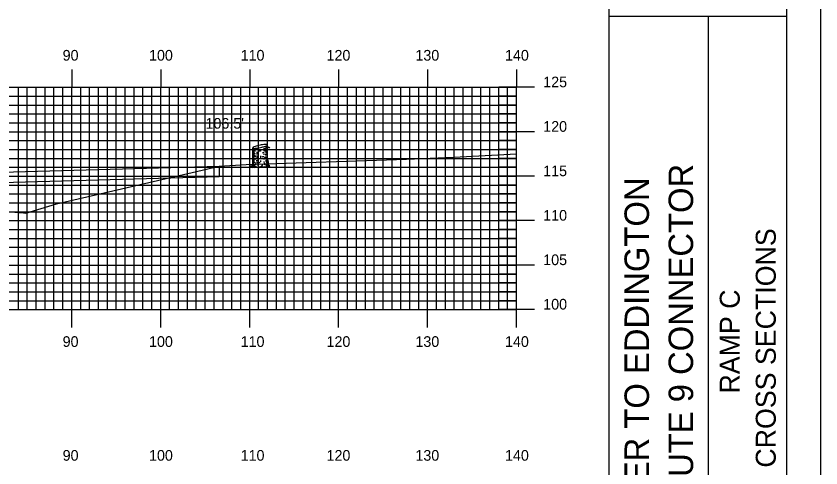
# Model space of a CAD drawing. Extents: x 1685586 to 1685929, y 461260 to 461480.
# Drawn here: x 1685835.5 to 1685926, y 461305.3 to 461356.1 of the extents above; entities that cross this region are included whole.
import ezdxf

# ---------------------------------------------------------------- set-up
doc = ezdxf.new("R2010")
doc.units = 0
for name, color, linetype in [('BORDER', 7, 'Continuous'), ('D_Roadway_Drive_Gravel_RT', 7, 'Continuous'), ('D_Text_Standard', 7, 'Continuous'), ('H_V ANNOTATION', 7, 'Continuous'), ('M_Trees_Conifer_Pay', 7, 'Continuous'), ('MAJOR', 7, 'Continuous'), ('MINOR', 7, 'Continuous'), ('PLOT BOUNDARY', 7, 'Continuous'), ('S_Roadway_Centerline', 7, 'Continuous')]:
    doc.layers.add(name, color=color, linetype=linetype)

msp = doc.modelspace()

# ---------------------------------------------------------------- linework, layer by layer
at = {"layer": 'BORDER'}
for p, q in [((1685902.142, 461266.072), (1685902.142, 461476.072)), ((1685902.142, 461356.078), (1685922.142, 461356.078)), ((1685913.325, 461286.078), (1685913.325, 461356.078))]:
    msp.add_line(p, q, dxfattribs=at)
msp.add_lwpolyline([(1685602.142, 461266.072), (1685922.142, 461266.072), (1685922.142, 461476.072), (1685602.142, 461476.072)], close=True, dxfattribs=at)
at = {"layer": 'D_Roadway_Drive_Gravel_RT'}
msp.add_line((1685858.314, 461339.198), (1685858.314, 461338.031), dxfattribs=at)
for points in [[(1685759.742, 461336.549), (1685765.742, 461336.669), (1685858.314, 461339.198)], [(1685765.742, 461335.502), (1685858.314, 461338.031)]]:
    msp.add_lwpolyline(points, dxfattribs=at)
at = {"layer": 'M_Trees_Conifer_Pay'}
for p, q in [((1685862.097, 461339.54), (1685862.097, 461341.262)), ((1685862.144, 461341.225), (1685862.144, 461340.753)), ((1685862.202, 461341.213), (1685862.202, 461341.116)), ((1685862.202, 461341.042), (1685862.202, 461340.837)), ((1685862.328, 461341.206), (1685862.328, 461340.973)), ((1685862.328, 461340.933), (1685862.328, 461340.858)), ((1685862.547, 461341.226), (1685862.547, 461341.058)), ((1685862.953, 461340.994), (1685862.953, 461340.899)), ((1685863.343, 461341.268), (1685863.343, 461341.068)), ((1685863.343, 461341.011), (1685863.343, 461340.922)), ((1685863.572, 461341.464), (1685863.572, 461341.241)), ((1685863.572, 461341.152), (1685863.572, 461341.105)), ((1685863.629, 461340.969), (1685863.578, 461340.91)), ((1685863.689, 461341.525), (1685863.689, 461341.362)), ((1685863.689, 461341.295), (1685863.689, 461341.167)), ((1685863.689, 461340.98), (1685863.689, 461340.644)), ((1685863.761, 461339.95), (1685863.761, 461341.597)), ((1685862.144, 461340.689), (1685862.144, 461340.381)), ((1685862.144, 461340.334), (1685862.144, 461339.841)), ((1685862.202, 461340.78), (1685862.202, 461340.58)), ((1685862.202, 461340.533), (1685862.202, 461340.197)), ((1685862.202, 461340.144), (1685862.202, 461340.008)), ((1685862.328, 461340.455), (1685862.328, 461340.316)), ((1685862.328, 461340.045), (1685862.328, 461339.903)), ((1685862.547, 461340.821), (1685862.547, 461340.584)), ((1685862.547, 461340.339), (1685862.547, 461340.187)), ((1685862.547, 461340.144), (1685862.547, 461339.971)), ((1685862.953, 461340.381), (1685862.953, 461340.307)), ((1685862.953, 461340.282), (1685862.953, 461340.133)), ((1685863.343, 461340.574), (1685863.343, 461340.469)), ((1685863.343, 461340.103), (1685863.343, 461339.956)), ((1685863.572, 461340.77), (1685863.572, 461340.638)), ((1685863.572, 461340.527), (1685863.572, 461340.418)), ((1685863.572, 461340.282), (1685863.572, 461340.14)), ((1685863.689, 461340.607), (1685863.689, 461340.444)), ((1685863.689, 461340.397), (1685863.689, 461340.181)), ((1685863.689, 461340.15), (1685863.689, 461340.076)), ((1685863.689, 461340.035), (1685863.689, 461339.862)), ((1685862.144, 461339.788), (1685862.144, 461339.54)), ((1685862.202, 461339.909), (1685862.202, 461339.53)), ((1685862.328, 461339.641), (1685862.328, 461339.547)), ((1685862.328, 461339.147), (1685862.49, 461339.211)), ((1685862.547, 461339.693), (1685862.547, 461339.54)), ((1685862.765, 461339.083), (1685862.639, 461339.147)), ((1685862.953, 461339.841), (1685862.953, 461339.689)), ((1685863.343, 461339.724), (1685863.343, 461339.635)), ((1685863.572, 461339.913), (1685863.572, 461339.74))]:
    msp.add_line(p, q, dxfattribs=at)
for points in [[(1685863.544, 461341.058), (1685863.513, 461340.973), (1685863.509, 461340.906), (1685863.54, 461340.842)], [(1685863.578, 461341.095), (1685863.614, 461341.021), (1685863.662, 461341.078), (1685863.719, 461341.147), (1685863.812, 461341.34), (1685863.876, 461341.387), (1685863.907, 461341.394)], [(1685863.592, 461340.842), (1685863.629, 461340.969), (1685863.692, 461341.085), (1685863.723, 461341.152), (1685863.792, 461341.299)], [(1685863.807, 461341.328), (1685863.882, 461341.336), (1685863.954, 461341.237)], [(1685862.276, 461340.568), (1685862.27, 461340.663), (1685862.313, 461340.64), (1685862.313, 461340.545)], [(1685863.415, 461340.169), (1685863.427, 461340.092), (1685863.475, 461340.103), (1685863.462, 461340.269)], [(1685863.761, 461339.95), (1685863.812, 461339.689), (1685863.828, 461339.415), (1685863.886, 461339.29), (1685864.022, 461339.259), (1685863.792, 461339.221), (1685863.792, 461339.221), (1685863.797, 461339.174), (1685864.045, 461339.08), (1685863.771, 461339.096), (1685863.415, 461339.116), (1685863.093, 461339.106), (1685863.1, 461339.189), (1685862.952, 461339.106), (1685862.765, 461339.083), (1685862.789, 461339.015), (1685862.521, 461339.059), (1685862.301, 461339.032), (1685862.008, 461339.049), (1685862.297, 461339.106), (1685862.328, 461339.147), (1685862.165, 461339.205), (1685861.928, 461339.215), (1685861.687, 461339.215), (1685862.029, 461339.273), (1685862.07, 461339.353), (1685862.097, 461339.54)], [(1685862.145, 461339.493), (1685862.124, 461339.415), (1685862.103, 461339.32)], [(1685862.223, 461339.473), (1685862.229, 461339.357), (1685862.175, 461339.269), (1685862.165, 461339.205)], [(1685862.385, 461339.5), (1685862.385, 461339.368), (1685862.297, 461339.269)], [(1685862.612, 461339.259), (1685862.679, 461339.353), (1685862.706, 461339.493)], [(1685863.1, 461339.189), (1685863.174, 461339.33), (1685863.184, 461339.431)], [(1685863.351, 461339.557), (1685863.361, 461339.431), (1685863.435, 461339.388)], [(1685863.629, 461339.168), (1685863.614, 461339.306), (1685863.54, 461339.435)], [(1685863.587, 461339.662), (1685863.662, 461339.557), (1685863.666, 461339.384), (1685863.792, 461339.221)], [(1685863.687, 461339.808), (1685863.692, 461339.662), (1685863.74, 461339.594), (1685863.75, 461339.395)]]:
    msp.add_lwpolyline(points, dxfattribs=at)
for centre, radius, start, end in [((1685862.129, 461341.084), 0.0334, 163.94846, 180), ((1685862.129, 461341.084), 0.0334, 180, 196.05154), ((1685862.128, 461341.261), 0.0314, 156.51582, 169.2194), ((1685862.123, 461341.262), 0.0264, 169.2194, 180.03145), ((1685862.119, 461341.262), 0.0226, 180.03145, 191.7194), ((1685862.119, 461341.262), 0.0226, 191.7194, 203.40735), ((1685862.139, 461341.087), 0.0441, 196.05154, 210), ((1685862.148, 461341.252), 0.0527, 146.7194, 156.51582), ((1685862.123, 461341.263), 0.0264, 203.40735, 214.2194), ((1685862.127, 461341.266), 0.0314, 214.2194, 226.92298), ((1685862.155, 461341.096), 0.0624, 210, 228.74941), ((1685862.172, 461341.236), 0.0817, 132.38868, 146.7194), ((1685862.142, 461341.282), 0.0527, 226.92298, 236.7194), ((1685862.157, 461341.306), 0.0817, 236.7194, 251.05013), ((1685862.227, 461341.178), 0.172, 228.74941, 240), ((1685862.286, 461341.112), 0.251, 124.2194, 132.38868), ((1685862.212, 461341.466), 0.251, 251.05013, 259.2194), ((1685862.427, 461341.524), 0.571, 240, 240.33672), ((1685862.596, 461340.656), 0.802, 108.05939, 124.2194), ((1685862.315, 461342.007), 0.802, 259.2194, 275.37941), ((1685862.427, 461341.524), 0.571, 246.85973, 257.98457), ((1685863.953, 461336.494), 5.179, 101.7194, 108.05939), ((1685861.905, 461346.365), 5.179, 275.37941, 281.7194), ((1685862.929, 461345.274), 4.124, 264.6955, 266.73309), ((1685862.927, 461345.041), 4.124, 268.07512, 270), ((1685863.953, 461336.494), 5.179, 95.37941, 101.7194), ((1685862.927, 461345.041), 4.124, 270, 270.35814), ((1685861.905, 461346.365), 5.179, 281.7194, 288.05939), ((1685862.927, 461345.041), 4.124, 275.78493, 277.05584), ((1685862.929, 461345.274), 4.124, 276.23804, 278.1032), ((1685863.542, 461340.852), 0.802, 79.2194, 95.37941), ((1685863.262, 461342.203), 0.802, 288.05939, 304.2194), ((1685863.43, 461341.756), 0.571, 278.1032, 284.36665), ((1685863.43, 461341.911), 0.571, 284.43166, 292.41325), ((1685863.43, 461341.756), 0.571, 297.0237, 300), ((1685863.645, 461341.394), 0.251, 71.05013, 79.2194), ((1685863.572, 461341.748), 0.251, 304.2194, 312.38868), ((1685863.629, 461341.566), 0.172, 300, 311.25059), ((1685863.629, 461341.411), 0.172, 300, 311.25059), ((1685863.7, 461341.553), 0.0817, 56.7194, 71.05013), ((1685863.686, 461341.623), 0.0817, 312.38868, 326.7194), ((1685863.701, 461341.483), 0.0624, 311.25059, 330), ((1685863.701, 461341.329), 0.0624, 311.25059, 330), ((1685863.716, 461341.578), 0.0527, 46.92298, 56.7194), ((1685863.731, 461341.593), 0.0314, 34.2194, 46.92298), ((1685863.71, 461341.607), 0.0527, 326.7194, 336.51582), ((1685863.717, 461341.474), 0.0441, 330, 343.94846), ((1685863.717, 461341.32), 0.0441, 330, 343.94846), ((1685863.735, 461341.596), 0.0264, 23.40735, 34.2194), ((1685863.729, 461341.598), 0.0314, 336.51582, 349.2194), ((1685863.738, 461341.598), 0.0226, 11.7194, 23.40735), ((1685863.738, 461341.598), 0.0226, 0.03145, 11.7194), ((1685863.734, 461341.598), 0.0264, 349.2194, 0.03145), ((1685863.728, 461341.471), 0.0334, 343.94846, 354.21506), ((1685863.728, 461341.317), 0.0334, 343.94846, 354.21506), ((1685862.129, 461340.637), 0.0334, 163.94846, 180), ((1685862.129, 461340.637), 0.0334, 180, 196.05154), ((1685862.129, 461340.427), 0.0334, 163.94846, 180), ((1685862.129, 461340.427), 0.0334, 180, 196.05154), ((1685862.129, 461340.19), 0.0334, 163.94846, 180), ((1685862.129, 461340.19), 0.0334, 180, 196.05154), ((1685862.129, 461339.992), 0.0334, 163.94846, 180), ((1685862.139, 461340.64), 0.0441, 196.05154, 210), ((1685862.139, 461340.43), 0.0441, 196.05154, 210), ((1685862.139, 461340.193), 0.0441, 196.05154, 210), ((1685862.155, 461340.649), 0.0624, 210, 228.74941), ((1685862.155, 461340.439), 0.0624, 210, 228.74941), ((1685862.155, 461340.202), 0.0624, 210, 228.74941), ((1685862.227, 461340.732), 0.172, 228.74941, 240), ((1685862.227, 461340.522), 0.172, 228.74941, 240), ((1685862.227, 461340.285), 0.172, 228.74941, 240), ((1685862.427, 461341.077), 0.571, 240, 240.33672), ((1685862.427, 461340.867), 0.571, 240, 246.85973), ((1685862.427, 461340.63), 0.571, 240, 246.85973), ((1685862.428, 461341.312), 0.571, 240, 247.05866), ((1685862.427, 461340.867), 0.571, 259.27072, 261.8968), ((1685862.927, 461344.384), 4.124, 261.8968, 263.14738), ((1685862.927, 461344.594), 4.124, 264.08098, 266.66759), ((1685862.927, 461344.147), 4.124, 264.71603, 266.31934), ((1685862.927, 461344.384), 4.124, 270, 270.35814), ((1685862.927, 461344.384), 4.124, 273.14934, 275.45691), ((1685862.929, 461344.83), 4.124, 273.70524, 275.95043), ((1685862.927, 461344.594), 4.124, 277.61247, 278.1032), ((1685863.428, 461341.077), 0.571, 278.1032, 286.92962), ((1685863.43, 461341.312), 0.571, 284.44928, 297.04285), ((1685863.428, 461340.63), 0.571, 285.39827, 297.18959), ((1685863.428, 461341.077), 0.571, 297.18959, 300), ((1685863.428, 461340.867), 0.571, 297.18959, 300), ((1685863.628, 461340.732), 0.172, 300, 311.25059), ((1685863.628, 461340.522), 0.172, 300, 311.25059), ((1685863.7, 461340.649), 0.0624, 311.25059, 330), ((1685863.7, 461340.439), 0.0624, 311.25059, 330), ((1685863.716, 461340.64), 0.0441, 330, 343.94846), ((1685863.716, 461340.43), 0.0441, 330, 343.94846), ((1685863.716, 461339.995), 0.0441, 330, 343.94846), ((1685863.726, 461340.637), 0.0334, 343.94846, 354.21506), ((1685863.726, 461340.427), 0.0334, 343.94846, 354.21506), ((1685863.726, 461339.992), 0.0334, 343.94846, 354.21506), ((1685863.727, 461340.873), 0.0334, 343.94846, 354.21506), ((1685862.129, 461339.797), 0.0334, 163.94846, 180), ((1685862.129, 461339.797), 0.0334, 180, 196.05154), ((1685862.129, 461339.577), 0.0334, 163.94846, 180), ((1685862.129, 461339.577), 0.0334, 180, 196.05154), ((1685862.139, 461339.8), 0.0441, 196.05154, 210), ((1685862.139, 461339.58), 0.0441, 196.05154, 210), ((1685862.155, 461339.809), 0.0624, 210, 228.74941), ((1685862.155, 461339.589), 0.0624, 210, 228.74941), ((1685862.227, 461339.892), 0.172, 228.74941, 240), ((1685862.227, 461339.671), 0.172, 228.74941, 240), ((1685862.416, 461340.438), 0.571, 241.23686, 248.02677), ((1685862.427, 461340.237), 0.571, 240, 246.85973), ((1685862.427, 461340.016), 0.571, 240, 244.53138), ((1685862.927, 461343.534), 4.124, 262.44379, 263.51202), ((1685862.927, 461343.95), 4.124, 263.49906, 265.83975), ((1685862.927, 461343.754), 4.124, 267.81166, 270), ((1685862.927, 461343.754), 4.124, 270, 270.13279), ((1685862.927, 461343.754), 4.124, 275.78493, 276.78961), ((1685862.927, 461343.534), 4.124, 277.36842, 278.1032), ((1685863.428, 461340.016), 0.571, 278.1032, 281.63703), ((1685863.428, 461340.237), 0.571, 288.50673, 297.27208), ((1685863.428, 461340.432), 0.571, 289.29072, 300), ((1685863.628, 461340.087), 0.172, 300, 311.25059), ((1685863.628, 461339.671), 0.172, 300, 311.25059), ((1685863.7, 461340.005), 0.0624, 311.25059, 330), ((1685863.7, 461339.589), 0.0624, 311.25059, 330), ((1685863.716, 461339.58), 0.0441, 330, 343.94846), ((1685863.726, 461339.577), 0.0334, 343.94846, 354.21506)]:
    msp.add_arc(centre, radius, start, end, dxfattribs=at)
at = {"layer": 'MAJOR'}
for p, q in [((1685841.742, 461350.076), (1685841.742, 461348.072)), ((1685851.742, 461350.076), (1685851.742, 461348.072)), ((1685861.742, 461350.076), (1685861.742, 461348.072)), ((1685871.742, 461350.076), (1685871.742, 461348.072)), ((1685881.742, 461350.076), (1685881.742, 461348.072)), ((1685891.742, 461350.076), (1685891.742, 461348.072)), ((1685611.742, 461348.072), (1685891.742, 461348.072)), ((1685611.742, 461348.072), (1685891.742, 461348.072)), ((1685841.742, 461323.072), (1685841.742, 461348.072)), ((1685851.742, 461323.072), (1685851.742, 461348.072)), ((1685861.742, 461323.072), (1685861.742, 461348.072)), ((1685871.742, 461323.072), (1685871.742, 461348.072)), ((1685881.742, 461323.072), (1685881.742, 461348.072)), ((1685893.746, 461348.072), (1685889.738, 461348.072)), ((1685891.742, 461323.072), (1685891.742, 461348.072)), ((1685891.742, 461323.072), (1685891.742, 461348.072)), ((1685611.742, 461343.072), (1685891.742, 461343.072)), ((1685893.746, 461343.072), (1685889.738, 461343.072)), ((1685611.742, 461338.072), (1685891.742, 461338.072)), ((1685893.746, 461338.072), (1685889.738, 461338.072)), ((1685611.742, 461333.072), (1685891.742, 461333.072)), ((1685893.746, 461333.072), (1685889.738, 461333.072)), ((1685611.742, 461328.072), (1685891.742, 461328.072)), ((1685893.746, 461328.072), (1685889.738, 461328.072)), ((1685611.742, 461323.072), (1685891.742, 461323.072)), ((1685611.742, 461323.072), (1685891.742, 461323.072)), ((1685841.742, 461321.068), (1685841.742, 461323.072)), ((1685851.742, 461321.068), (1685851.742, 461323.072)), ((1685861.742, 461321.068), (1685861.742, 461323.072)), ((1685871.742, 461321.068), (1685871.742, 461323.072)), ((1685881.742, 461321.068), (1685881.742, 461323.072)), ((1685893.746, 461323.072), (1685889.738, 461323.072)), ((1685891.742, 461321.068), (1685891.742, 461323.072))]:
    msp.add_line(p, q, dxfattribs=at)
at = {"layer": 'MINOR'}
for p, q in [((1685835.742, 461323.072), (1685835.742, 461348.072)), ((1685836.742, 461323.072), (1685836.742, 461348.072)), ((1685837.742, 461323.072), (1685837.742, 461348.072)), ((1685838.742, 461323.072), (1685838.742, 461348.072)), ((1685839.742, 461323.072), (1685839.742, 461348.072)), ((1685840.742, 461323.072), (1685840.742, 461348.072)), ((1685842.742, 461323.072), (1685842.742, 461348.072)), ((1685843.742, 461323.072), (1685843.742, 461348.072)), ((1685844.742, 461323.072), (1685844.742, 461348.072)), ((1685845.742, 461323.072), (1685845.742, 461348.072)), ((1685846.742, 461323.072), (1685846.742, 461348.072)), ((1685847.742, 461323.072), (1685847.742, 461348.072)), ((1685848.742, 461323.072), (1685848.742, 461348.072)), ((1685849.742, 461323.072), (1685849.742, 461348.072)), ((1685850.742, 461323.072), (1685850.742, 461348.072)), ((1685852.742, 461323.072), (1685852.742, 461348.072)), ((1685853.742, 461323.072), (1685853.742, 461348.072)), ((1685854.742, 461323.072), (1685854.742, 461348.072)), ((1685855.742, 461323.072), (1685855.742, 461348.072)), ((1685856.742, 461323.072), (1685856.742, 461348.072)), ((1685857.742, 461323.072), (1685857.742, 461348.072)), ((1685858.742, 461323.072), (1685858.742, 461348.072)), ((1685859.742, 461323.072), (1685859.742, 461348.072)), ((1685860.742, 461323.072), (1685860.742, 461348.072)), ((1685862.742, 461323.072), (1685862.742, 461348.072)), ((1685863.742, 461323.072), (1685863.742, 461348.072)), ((1685864.742, 461323.072), (1685864.742, 461348.072)), ((1685865.742, 461323.072), (1685865.742, 461348.072)), ((1685866.742, 461323.072), (1685866.742, 461348.072)), ((1685867.742, 461323.072), (1685867.742, 461348.072)), ((1685868.742, 461323.072), (1685868.742, 461348.072)), ((1685869.742, 461323.072), (1685869.742, 461348.072)), ((1685870.742, 461323.072), (1685870.742, 461348.072)), ((1685872.742, 461323.072), (1685872.742, 461348.072)), ((1685873.742, 461323.072), (1685873.742, 461348.072)), ((1685874.742, 461323.072), (1685874.742, 461348.072)), ((1685875.742, 461323.072), (1685875.742, 461348.072)), ((1685876.742, 461323.072), (1685876.742, 461348.072)), ((1685877.742, 461323.072), (1685877.742, 461348.072)), ((1685878.742, 461323.072), (1685878.742, 461348.072)), ((1685879.742, 461323.072), (1685879.742, 461348.072)), ((1685880.742, 461323.072), (1685880.742, 461348.072)), ((1685882.742, 461323.072), (1685882.742, 461348.072)), ((1685883.742, 461323.072), (1685883.742, 461348.072)), ((1685884.742, 461323.072), (1685884.742, 461348.072)), ((1685885.742, 461323.072), (1685885.742, 461348.072)), ((1685886.742, 461323.072), (1685886.742, 461348.072)), ((1685887.742, 461323.072), (1685887.742, 461348.072)), ((1685888.742, 461323.072), (1685888.742, 461348.072)), ((1685889.742, 461323.072), (1685889.742, 461348.072)), ((1685890.742, 461323.072), (1685890.742, 461348.072)), ((1685611.742, 461347.072), (1685891.742, 461347.072)), ((1685891.742, 461347.072), (1685889.738, 461347.072)), ((1685611.742, 461346.072), (1685891.742, 461346.072)), ((1685891.742, 461346.072), (1685889.738, 461346.072)), ((1685611.742, 461345.072), (1685891.742, 461345.072)), ((1685891.742, 461345.072), (1685889.738, 461345.072)), ((1685611.742, 461344.072), (1685891.742, 461344.072)), ((1685891.742, 461344.072), (1685889.738, 461344.072)), ((1685611.742, 461342.072), (1685891.742, 461342.072)), ((1685891.742, 461342.072), (1685889.738, 461342.072)), ((1685611.742, 461341.072), (1685891.742, 461341.072)), ((1685891.742, 461341.072), (1685889.738, 461341.072)), ((1685611.742, 461340.072), (1685891.742, 461340.072)), ((1685891.742, 461340.072), (1685889.738, 461340.072)), ((1685611.742, 461339.072), (1685891.742, 461339.072)), ((1685891.742, 461339.072), (1685889.738, 461339.072)), ((1685611.742, 461337.072), (1685891.742, 461337.072)), ((1685891.742, 461337.072), (1685889.738, 461337.072)), ((1685611.742, 461336.072), (1685891.742, 461336.072)), ((1685891.742, 461336.072), (1685889.738, 461336.072)), ((1685611.742, 461335.072), (1685891.742, 461335.072)), ((1685891.742, 461335.072), (1685889.738, 461335.072)), ((1685611.742, 461334.072), (1685891.742, 461334.072)), ((1685891.742, 461334.072), (1685889.738, 461334.072)), ((1685611.742, 461332.072), (1685891.742, 461332.072)), ((1685891.742, 461332.072), (1685889.738, 461332.072)), ((1685611.742, 461331.072), (1685891.742, 461331.072)), ((1685891.742, 461331.072), (1685889.738, 461331.072)), ((1685611.742, 461330.072), (1685891.742, 461330.072)), ((1685891.742, 461330.072), (1685889.738, 461330.072)), ((1685611.742, 461329.072), (1685891.742, 461329.072)), ((1685891.742, 461329.072), (1685889.738, 461329.072)), ((1685611.742, 461327.072), (1685891.742, 461327.072)), ((1685891.742, 461327.072), (1685889.738, 461327.072)), ((1685611.742, 461326.072), (1685891.742, 461326.072)), ((1685891.742, 461326.072), (1685889.738, 461326.072)), ((1685611.742, 461325.072), (1685891.742, 461325.072)), ((1685891.742, 461325.072), (1685889.738, 461325.072)), ((1685611.742, 461324.072), (1685891.742, 461324.072)), ((1685891.742, 461324.072), (1685889.738, 461324.072))]:
    msp.add_line(p, q, dxfattribs=at)
at = {"layer": 'PLOT BOUNDARY'}
msp.add_lwpolyline([(1685585.956, 461259.954), (1685925.956, 461259.954), (1685925.956, 461479.954), (1685585.956, 461479.954)], close=True, dxfattribs=at)
at = {"layer": 'S_Roadway_Centerline'}
msp.add_lwpolyline([(1685832.399, 461334.246), (1685836.327, 461333.95), (1685836.576, 461333.928), (1685840.019, 461334.96), (1685855.271, 461338.483), (1685858.314, 461339.198), (1685861.346, 461339.37), (1685879.377, 461339.979), (1685884.677, 461340.227), (1685891.742, 461340.587)], dxfattribs=at)

# ---------------------------------------------------------------- texts
at = {"layer": 'BORDER'}
for s, height, p in [('1-395/ROUTE 9 CONNECTOR', 2.75575, (1685911.592, 461288.272)), ('BREWER TO EDDINGTON', 2.75575, (1685906.631, 461292.481)), ('CROSS SECTIONS', 2.25, (1685920.884, 461305.294)), ('RAMP C', 2.25, (1685916.834, 461313.629))]:
    msp.add_text(s, height=height, rotation=90, dxfattribs=at).set_placement(p)
at = {"layer": 'D_Text_Standard'}
msp.add_text("106.5'", height=1.2, dxfattribs=at).set_placement((1685856.773, 461343.417))
at = {"layer": 'H_V ANNOTATION'}
for s, p in [('90', (1685840.715, 461351.072)), ('100', (1685850.426, 461351.072)), ('110', (1685860.726, 461351.072)), ('120', (1685870.383, 461351.072)), ('130', (1685880.372, 461351.072)), ('140', (1685890.447, 461351.072)), ('125', (1685894.742, 461348.072)), ('120', (1685894.742, 461343.072)), ('115', (1685894.742, 461338.072)), ('110', (1685894.742, 461333.072)), ('105', (1685894.742, 461328.072)), ('100', (1685894.742, 461323.072)), ('90', (1685840.715, 461318.872)), ('100', (1685850.426, 461318.872)), ('110', (1685860.726, 461318.872)), ('120', (1685870.383, 461318.872)), ('130', (1685880.372, 461318.872)), ('140', (1685890.447, 461318.872)), ('90', (1685840.715, 461306.072)), ('100', (1685850.426, 461306.072)), ('110', (1685860.726, 461306.072)), ('120', (1685870.383, 461306.072)), ('130', (1685880.372, 461306.072)), ('140', (1685890.447, 461306.072))]:
    msp.add_text(s, height=1.2, dxfattribs=at).set_placement(p)

doc.saveas('drawing.dxf')
